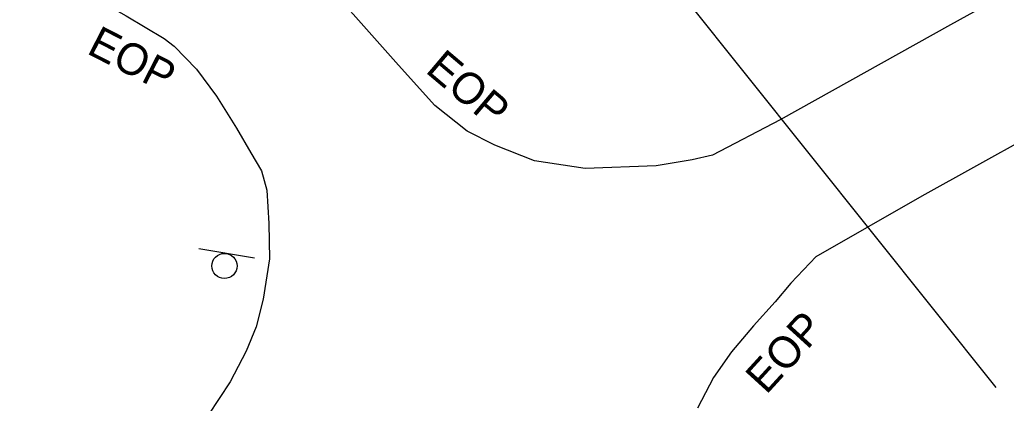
# Model space of a CAD drawing. Extents: x 2076109 to 2080761, y 592812 to 596750.
# Drawn here: x 2077739.5 to 2077896.2, y 596055.5 to 596116.5 of the extents above; entities that cross this region are included whole.
import ezdxf

# ---------------------------------------------------------------- set-up
doc = ezdxf.new("R2010")
doc.units = 0
for name, color, linetype in [('RD_EX_BldgApp', 7, 'Continuous'), ('RD_EX_Road', 7, 'Continuous'), ('RD_EX_Road_txCode', 7, 'Continuous'), ('RD_EX_UT', 7, 'Continuous')]:
    doc.layers.add(name, color=color, linetype=linetype)

msp = doc.modelspace()

# ---------------------------------------------------------------- linework, layer by layer
at = {"layer": 'RD_EX_BldgApp'}
msp.add_line((2077776.82, 596078.62), (2077767.94, 596080.09), dxfattribs=at)
msp.add_line((2077776.82, 596078.62), (2077767.94, 596080.09), dxfattribs=at)
msp.add_circle((2077772.03, 596077.36), 2, dxfattribs=at)
msp.add_circle((2077772.03, 596077.36), 2, dxfattribs=at)
at = {"layer": 'RD_EX_Road'}
for points in [[(2077866, 596078.88), (2077882.82, 596088.5), (2077908.39, 596102.7), (2077940, 596120.34), (2077965.56, 596134.84), (2077993.91, 596150.64), (2078020.83, 596165.73), (2078053.47, 596183.92), (2078082.23, 596200.16), (2078111.12, 596216.43), (2078136.34, 596230.7), (2078157.72, 596242.66), (2078180, 596255.29), (2078191.26, 596261.54)], [(2077866, 596078.88), (2077882.82, 596088.5), (2077908.39, 596102.7), (2077940, 596120.34), (2077965.56, 596134.84), (2077993.91, 596150.64), (2078020.83, 596165.73), (2078053.47, 596183.92), (2078082.23, 596200.16), (2078111.12, 596216.43), (2078136.34, 596230.7), (2078157.72, 596242.66), (2078180, 596255.29), (2078191.26, 596261.54)], [(2077910.17, 596128.35), (2077887.33, 596115.65), (2077860.29, 596100.58), (2077849.55, 596094.96), (2077846.3, 596094.21), (2077840.58, 596093.26), (2077829.29, 596092.85), (2077821.25, 596094.04), (2077814.95, 596096.53), (2077810.58, 596098.8), (2077805.43, 596102.88), (2077799.67, 596109.27), (2077784.81, 596126.08), (2077777.76, 596132.41), (2077773.78, 596135.42), (2077767.37, 596139.74), (2077758.76, 596144.4), (2077751.46, 596147.55), (2077746.86, 596149.01), (2077740.04, 596150.73), (2077731.71, 596151.8)], [(2077910.17, 596128.35), (2077887.33, 596115.65), (2077860.29, 596100.58), (2077849.55, 596094.96), (2077846.3, 596094.21), (2077840.58, 596093.26), (2077829.29, 596092.85), (2077821.25, 596094.04), (2077814.95, 596096.53), (2077810.58, 596098.8), (2077805.43, 596102.88), (2077799.67, 596109.27), (2077784.81, 596126.08), (2077777.76, 596132.41), (2077773.78, 596135.42), (2077767.37, 596139.74), (2077758.76, 596144.4), (2077751.46, 596147.55), (2077746.86, 596149.01), (2077740.04, 596150.73), (2077731.71, 596151.8)], [(2077735.96, 596126.24), (2077743.91, 596123.42), (2077751.7, 596119.81), (2077756.43, 596117.1), (2077762.46, 596113.52), (2077764.03, 596112.28), (2077767.62, 596108.64), (2077770.79, 596104.35), (2077773.97, 596099.27), (2077776.22, 596095.35), (2077777.9, 596092.5), (2077778.75, 596089.38), (2077779.09, 596084.09), (2077779.16, 596078.47), (2077778.18, 596072.09), (2077777.07, 596067.69), (2077775.48, 596063.8), (2077772.92, 596058.93), (2077769.46, 596053.64)], [(2077735.96, 596126.24), (2077743.91, 596123.42), (2077751.7, 596119.81), (2077756.43, 596117.1), (2077762.46, 596113.52), (2077764.03, 596112.28), (2077767.62, 596108.64), (2077770.79, 596104.35), (2077773.97, 596099.27), (2077776.22, 596095.35), (2077777.9, 596092.5), (2077778.75, 596089.38), (2077779.09, 596084.09), (2077779.16, 596078.47), (2077778.18, 596072.09), (2077777.07, 596067.69), (2077775.48, 596063.8), (2077772.92, 596058.93), (2077769.46, 596053.64)], [(2077866, 596078.88), (2077861.96, 596074.6), (2077859.49, 596071.68), (2077856.03, 596067.85), (2077852.52, 596063.71), (2077849.67, 596059.65), (2077847.15, 596054.79)], [(2077866, 596078.88), (2077861.96, 596074.6), (2077859.49, 596071.68), (2077856.03, 596067.85), (2077852.52, 596063.71), (2077849.67, 596059.65), (2077847.15, 596054.79)]]:
    msp.add_lwpolyline(points, dxfattribs=at)
at = {"layer": 'RD_EX_UT'}
msp.add_line((2077792.66, 596185.63), (2077894.53, 596058.05), dxfattribs=at)
msp.add_line((2077792.66, 596185.63), (2077894.53, 596058.05), dxfattribs=at)

# ---------------------------------------------------------------- texts
at = {"layer": 'RD_EX_Road_txCode'}
for rotation, p in [(332.8583, (2077749.99, 596111.22)), (332.8583, (2077749.99, 596111.22)), (319.7592, (2077803.78, 596108.24)), (319.7592, (2077803.78, 596108.24)), (47.6393, (2077858.06, 596056.8)), (47.6393, (2077858.06, 596056.8))]:
    msp.add_text('EOP', height=5, rotation=rotation, dxfattribs=at).set_placement(p)

doc.saveas('drawing.dxf')
